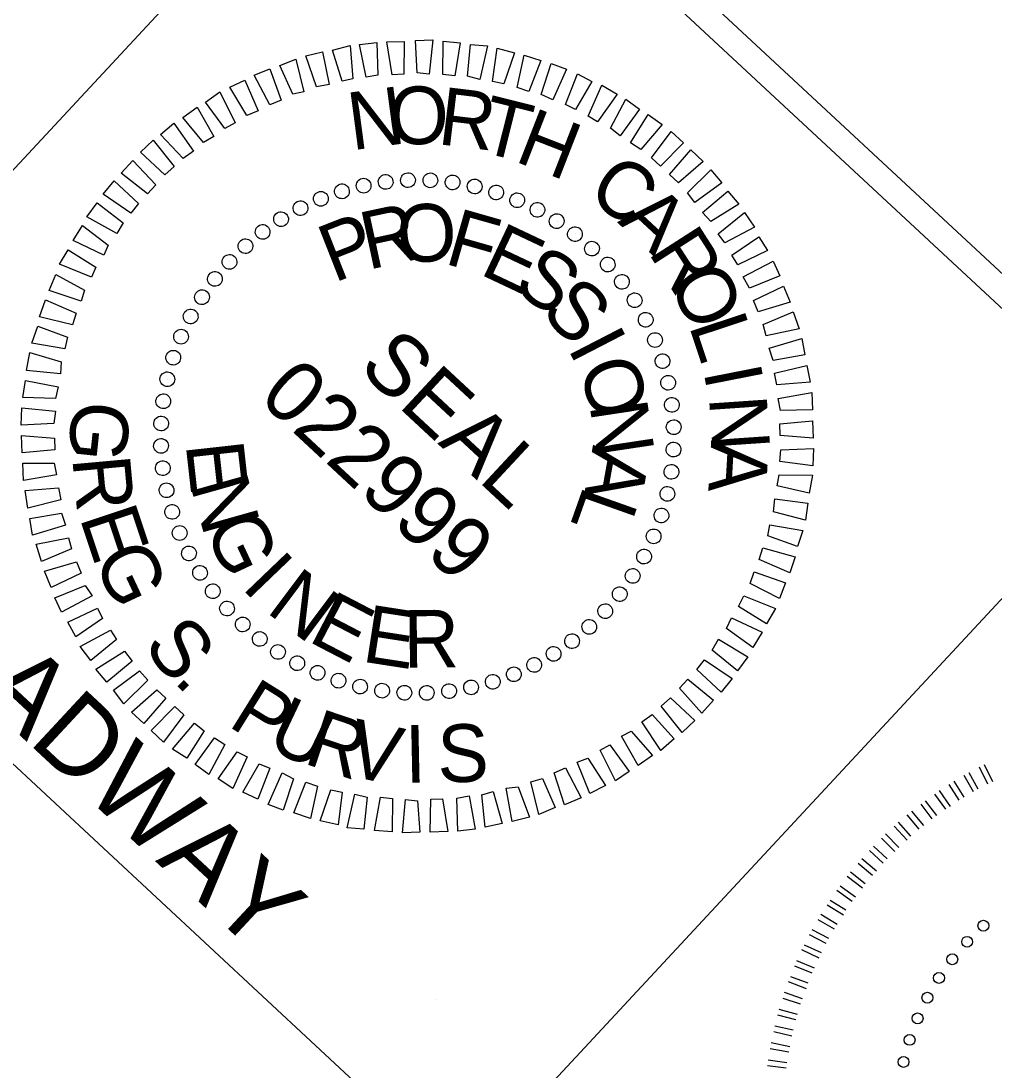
# Model space of a CAD drawing. Extents: x 2057696 to 2061410, y 685900 to 689434.
# Drawn here: x 2059112.8 to 2059188.9, y 688515.7 to 688597.9 of the extents above; entities that cross this region are included whole.
import ezdxf

# ---------------------------------------------------------------- set-up
doc = ezdxf.new("R2010")
doc.units = 0
for name, color, linetype in [('Default', 7, 'Continuous'), ('Exist Vertical Profile Vertical Axis Label', 7, 'Continuous'), ('Prop SS Fill Line', 7, 'Continuous'), ('Prop SS Misc', 7, 'Continuous'), ('Prop Vertical Profile Curve Label', 7, 'Continuous')]:
    doc.layers.add(name, color=color, linetype=linetype)

msp = doc.modelspace()

# ---------------------------------------------------------------- linework, layer by layer
at = {"layer": 'Default'}
for p, q in [((2059256.982, 688512.703), (2058378.024, 689329.669)), ((2059142.648, 688618.973), (2059089.028, 688561.283)), ((2059200.863, 688564.864), (2058628.797, 687949.389)), ((2059089.028, 688561.283), (2059203.361, 688455.014))]:
    msp.add_line(p, q, dxfattribs=at)
msp.add_lwpolyline([(2057714.84, 688796.536), (2058691.069, 687889.16), (2059265.668, 688507.36), (2058289.439, 689414.737)], close=True, dxfattribs=at)
at = {"layer": 'Exist Vertical Profile Vertical Axis Label'}
for p, q in [((2059187.702, 688537.79), (2059186.992, 688539.065)), ((2059188.458, 688538.163), (2059187.799, 688539.492)), ((2059188.849, 688538.363), (2059188.19, 688539.692)), ((2059186.222, 688536.913), (2059185.433, 688538.158)), ((2059186.611, 688537.167), (2059185.822, 688538.411)), ((2059187.339, 688537.565), (2059186.602, 688538.864)), ((2059185.159, 688536.211), (2059184.32, 688537.401)), ((2059185.523, 688536.437), (2059184.681, 688537.68)), ((2059184.099, 688535.456), (2059183.234, 688536.619)), ((2059184.46, 688535.735), (2059183.57, 688536.87)), ((2059183.094, 688534.65), (2059182.15, 688535.783)), ((2059183.455, 688534.928), (2059182.511, 688536.061)), ((2059182.143, 688533.792), (2059181.121, 688534.896)), ((2059182.424, 688534.095), (2059181.455, 688535.2)), ((2059181.501, 688533.212), (2059180.453, 688534.288)), ((2059180.578, 688532.329), (2059179.507, 688533.324)), ((2059181.167, 688532.908), (2059180.147, 688533.958)), ((2059180.272, 688531.999), (2059179.2, 688532.995)), ((2059179.431, 688531.04), (2059178.309, 688531.98)), ((2059179.737, 688531.369), (2059178.588, 688532.336)), ((2059178.645, 688530.029), (2059177.444, 688530.94)), ((2059178.871, 688530.382), (2059177.723, 688531.296)), ((2059178.113, 688529.346), (2059176.914, 688530.205)), ((2059177.834, 688528.991), (2059176.635, 688529.849)), ((2059177.156, 688527.931), (2059175.881, 688528.707)), ((2059177.355, 688528.31), (2059176.132, 688529.088)), ((2059176.453, 688526.844), (2059175.18, 688527.567)), ((2059176.679, 688527.197), (2059175.403, 688527.973)), ((2059176.029, 688526.112), (2059174.704, 688526.78)), ((2059175.805, 688525.706), (2059174.506, 688526.402)), ((2059175.262, 688524.572), (2059173.912, 688525.212)), ((2059175.433, 688524.976), (2059174.111, 688525.591)), ((2059174.893, 688523.789), (2059173.519, 688524.349)), ((2059174.722, 688523.384), (2059173.348, 688523.944)), ((2059174.262, 688522.173), (2059172.863, 688522.706)), ((2059174.406, 688522.603), (2059173.034, 688523.11)), ((2059173.946, 688521.392), (2059172.548, 688521.872)), ((2059173.802, 688520.963), (2059172.432, 688521.417)), ((2059173.448, 688519.755), (2059172.029, 688520.102)), ((2059173.566, 688520.158), (2059172.145, 688520.557)), ((2059173.124, 688518.47), (2059171.705, 688518.816)), ((2059173.24, 688518.925), (2059171.795, 688519.244)), ((2059172.968, 688517.642), (2059171.498, 688517.933)), ((2059172.878, 688517.214), (2059171.435, 688517.479)), ((2059172.685, 688515.959), (2059171.219, 688516.145)), ((2059172.722, 688516.385), (2059171.282, 688516.598))]:
    msp.add_line(p, q, dxfattribs=at)
for centre in [(2059188.109, 688527.102), (2059186.834, 688525.844), (2059185.672, 688524.479), (2059184.634, 688523.018), (2059183.727, 688521.473), (2059182.959, 688519.854), (2059182.334, 688518.174), (2059181.859, 688516.446)]:
    msp.add_circle(centre, 0.425, dxfattribs=at)
at = {"layer": 'Prop SS Misc'}
for p, q in [((2059139.656, 688585.001), (2059139.656, 688585.001)), ((2059141.344, 688585.289), (2059141.344, 688585.289)), ((2059143.094, 688585.409), (2059143.094, 688585.409)), ((2059144.849, 688585.417), (2059144.849, 688585.417)), ((2059146.582, 688585.225), (2059146.582, 688585.225)), ((2059137.918, 688584.541), (2059137.918, 688584.541)), ((2059148.32, 688584.921), (2059148.32, 688584.921)), ((2059150.007, 688584.445), (2059150.007, 688584.445)), ((2059136.297, 688583.972), (2059136.297, 688583.972)), ((2059151.669, 688583.883), (2059151.669, 688583.883)), ((2059134.71, 688583.263), (2059134.71, 688583.263)), ((2059153.226, 688583.091), (2059153.226, 688583.091)), ((2059133.185, 688582.387), (2059133.185, 688582.387)), ((2059154.759, 688582.213), (2059154.759, 688582.213)), ((2059131.723, 688581.342), (2059131.723, 688581.342)), ((2059156.182, 688581.218), (2059156.182, 688581.218)), ((2059130.404, 688580.275), (2059130.404, 688580.275)), ((2059157.525, 688580.078), (2059157.525, 688580.078)), ((2059129.147, 688579.041), (2059129.147, 688579.041)), ((2059158.76, 688578.821), (2059158.76, 688578.821)), ((2059128.007, 688577.697), (2059128.007, 688577.697)), ((2059159.857, 688577.474), (2059159.857, 688577.474)), ((2059126.985, 688576.245), (2059126.985, 688576.245)), ((2059160.844, 688576.01), (2059160.844, 688576.01)), ((2059126.105, 688574.769), (2059126.105, 688574.769)), ((2059161.748, 688574.515), (2059161.748, 688574.515)), ((2059125.342, 688573.184), (2059125.342, 688573.184)), ((2059162.43, 688572.898), (2059162.43, 688572.898)), ((2059124.751, 688571.549), (2059124.751, 688571.549)), ((2059163.028, 688571.25), (2059163.028, 688571.25)), ((2059124.248, 688569.833), (2059124.248, 688569.833)), ((2059163.458, 688569.54), (2059163.458, 688569.54)), ((2059123.97, 688568.125), (2059123.97, 688568.125)), ((2059163.776, 688567.825), (2059163.776, 688567.825)), ((2059123.752, 688566.362), (2059123.752, 688566.362)), ((2059163.896, 688566.074), (2059163.896, 688566.074)), ((2059143.855, 688565.37), (2059143.855, 688565.37)), ((2059123.759, 688564.607), (2059123.759, 688564.607)), ((2059163.904, 688564.32), (2059163.904, 688564.32)), ((2059123.88, 688562.857), (2059123.88, 688562.857)), ((2059163.74, 688562.616), (2059163.74, 688562.616)), ((2059124.197, 688561.142), (2059124.197, 688561.142)), ((2059163.408, 688560.849), (2059163.408, 688560.849)), ((2059124.628, 688559.431), (2059124.628, 688559.431)), ((2059162.959, 688559.191), (2059162.959, 688559.191)), ((2059125.226, 688557.783), (2059125.226, 688557.783)), ((2059162.368, 688557.556), (2059162.368, 688557.556)), ((2059125.962, 688556.225), (2059125.962, 688556.225)), ((2059161.605, 688555.971), (2059161.605, 688555.971)), ((2059126.811, 688554.671), (2059126.811, 688554.671)), ((2059160.67, 688554.437), (2059160.67, 688554.437)), ((2059127.853, 688553.266), (2059127.853, 688553.266)), ((2059159.702, 688553.043), (2059159.702, 688553.043)), ((2059128.95, 688551.919), (2059128.95, 688551.919)), ((2059158.563, 688551.7), (2059158.563, 688551.7)), ((2059130.184, 688550.662), (2059130.184, 688550.662)), ((2059157.306, 688550.465), (2059157.306, 688550.465)), ((2059131.528, 688549.523), (2059131.528, 688549.523)), ((2059155.932, 688549.339), (2059155.932, 688549.339)), ((2059132.951, 688548.527), (2059132.951, 688548.527)), ((2059154.525, 688548.354), (2059154.525, 688548.354)), ((2059134.429, 688547.591), (2059134.429, 688547.591)), ((2059153, 688547.477), (2059153, 688547.477)), ((2059136.041, 688546.857), (2059136.041, 688546.857)), ((2059151.413, 688546.768), (2059151.413, 688546.768)), ((2059137.648, 688546.237), (2059137.648, 688546.237)), ((2059139.336, 688545.761), (2059139.336, 688545.761)), ((2059148.054, 688545.74), (2059148.054, 688545.74)), ((2059149.737, 688546.141), (2059149.737, 688546.141)), ((2059141.073, 688545.456), (2059141.073, 688545.456)), ((2059142.807, 688545.265), (2059142.807, 688545.265)), ((2059144.561, 688545.272), (2059144.561, 688545.272)), ((2059146.312, 688545.393), (2059146.312, 688545.393)), ((2059145.295, 688521.326), (2059145.295, 688521.326))]:
    msp.add_line(p, q, dxfattribs=at)
for points in [[(2059137.943, 688593.146), (2059137.203, 688595.581), (2059138.577, 688595.943), (2059138.785, 688593.346)], [(2059139.828, 688593.469), (2059139.31, 688596.026), (2059140.662, 688596.189), (2059140.728, 688593.616)], [(2059141.859, 688593.657), (2059141.454, 688596.218), (2059142.81, 688596.267), (2059142.763, 688593.69)], [(2059143.806, 688593.813), (2059143.686, 688596.328), (2059145.042, 688596.377), (2059144.744, 688593.706)], [(2059145.82, 688593.688), (2059145.838, 688596.293), (2059147.174, 688596.144), (2059146.758, 688593.581)], [(2059147.75, 688593.533), (2059147.998, 688596.032), (2059149.305, 688595.91), (2059148.722, 688593.285)], [(2059149.718, 688593.123), (2059150.075, 688595.74), (2059151.419, 688595.365), (2059150.602, 688592.958)], [(2059134.103, 688592.128), (2059133.086, 688594.383), (2059134.314, 688594.881), (2059134.945, 688592.329)], [(2059135.95, 688592.705), (2059135.097, 688595.136), (2059136.416, 688595.439), (2059136.934, 688592.883)], [(2059151.632, 688592.656), (2059152.19, 688595.195), (2059153.479, 688594.761), (2059152.548, 688592.349)], [(2059132.293, 688591.298), (2059131.076, 688593.631), (2059132.303, 688594.128), (2059133.186, 688591.67)], [(2059153.52, 688592.102), (2059154.308, 688594.537), (2059155.485, 688594.098), (2059154.441, 688591.683)], [(2059130.484, 688590.467), (2059129.158, 688592.683), (2059130.326, 688593.235), (2059131.376, 688590.84)], [(2059155.416, 688591.322), (2059156.347, 688593.734), (2059157.473, 688593.124), (2059156.195, 688590.926)], [(2059157.204, 688590.425), (2059158.248, 688592.841), (2059159.462, 688592.149), (2059157.928, 688589.971)], [(2059128.767, 688589.442), (2059127.248, 688591.51), (2059128.379, 688592.315), (2059129.571, 688589.896)], [(2059158.937, 688589.47), (2059160.127, 688591.749), (2059161.203, 688590.968), (2059159.695, 688588.875)], [(2059127.108, 688588.363), (2059125.48, 688590.313), (2059126.611, 688591.118), (2059127.912, 688588.817)], [(2059160.507, 688588.338), (2059161.898, 688590.54), (2059162.974, 688589.759), (2059161.319, 688587.802)], [(2059125.512, 688587.116), (2059123.746, 688588.976), (2059124.789, 688589.863), (2059126.312, 688587.683)], [(2059162.135, 688587.152), (2059163.673, 688589.218), (2059164.64, 688588.32), (2059162.838, 688586.499)], [(2059124.088, 688585.818), (2059122.183, 688587.588), (2059123.168, 688588.53), (2059124.8, 688586.467)], [(2059163.541, 688585.845), (2059165.226, 688587.775), (2059166.192, 688586.876), (2059164.245, 688585.192)], [(2059122.726, 688584.353), (2059120.658, 688585.948), (2059121.584, 688586.944), (2059123.38, 688585.057)], [(2059164.952, 688584.425), (2059166.783, 688586.219), (2059167.64, 688585.203), (2059165.546, 688583.654)], [(2059121.423, 688582.834), (2059119.246, 688584.311), (2059120.114, 688585.362), (2059122.018, 688583.592)], [(2059166.14, 688582.884), (2059168.118, 688584.541), (2059168.975, 688583.525), (2059166.789, 688582.171)], [(2059120.321, 688581.237), (2059117.981, 688582.538), (2059118.79, 688583.643), (2059120.828, 688582.076)], [(2059167.362, 688581.202), (2059169.423, 688582.89), (2059170.202, 688581.73), (2059167.869, 688580.513)], [(2059119.307, 688579.558), (2059116.916, 688580.688), (2059117.637, 688581.875), (2059119.646, 688580.335)], [(2059168.442, 688579.543), (2059170.54, 688580.978), (2059171.231, 688579.9), (2059168.894, 688578.795)], [(2059118.351, 688577.825), (2059115.852, 688578.838), (2059116.518, 688579.966), (2059118.691, 688578.602)], [(2059169.324, 688577.849), (2059171.657, 688579.066), (2059172.18, 688577.925), (2059169.81, 688576.961)], [(2059117.542, 688575.956), (2059115.022, 688576.77), (2059115.542, 688578.034), (2059117.794, 688576.814)], [(2059170.128, 688576.01), (2059172.465, 688577.114), (2059172.992, 688575.86), (2059170.5, 688575.118)], [(2059116.846, 688574.091), (2059114.276, 688574.733), (2059114.737, 688576.052), (2059117.152, 688575.008)], [(2059170.876, 688574.113), (2059173.217, 688575.104), (2059173.69, 688573.791), (2059171.106, 688573.244)], [(2059116.263, 688572.23), (2059113.672, 688572.673), (2059114.133, 688573.992), (2059116.456, 688573.143)], [(2059171.34, 688572.262), (2059173.916, 688573.035), (2059174.133, 688571.741), (2059171.658, 688571.311)], [(2059115.911, 688570.264), (2059113.269, 688570.535), (2059113.529, 688571.932), (2059115.961, 688571.2)], [(2059171.779, 688570.325), (2059174.304, 688570.927), (2059174.551, 688569.605), (2059171.954, 688569.397)], [(2059115.529, 688568.325), (2059112.979, 688568.402), (2059113.184, 688569.74), (2059115.722, 688569.238)], [(2059172.05, 688568.325), (2059174.693, 688568.818), (2059174.742, 688567.461), (2059172.225, 688567.398)], [(2059115.402, 688566.368), (2059112.831, 688566.246), (2059112.894, 688567.606), (2059115.537, 688567.335)], [(2059172.179, 688566.349), (2059174.746, 688566.584), (2059174.795, 688565.227), (2059172.212, 688565.444)], [(2059115.476, 688564.333), (2059112.909, 688564.097), (2059112.86, 688565.454), (2059115.443, 688565.237)], [(2059172.253, 688564.314), (2059174.824, 688564.436), (2059174.761, 688563.075), (2059172.173, 688563.405)], [(2059115.605, 688562.356), (2059113.017, 688561.922), (2059112.968, 688563.279), (2059115.43, 688563.284)], [(2059172.127, 688562.356), (2059174.731, 688562.338), (2059174.471, 688560.942), (2059171.988, 688561.502)], [(2059115.931, 688560.415), (2059113.351, 688559.755), (2059113.159, 688561.135), (2059115.756, 688561.343)], [(2059171.799, 688560.476), (2059174.387, 688560.146), (2059174.181, 688558.808), (2059171.694, 688559.482)], [(2059116.315, 688558.42), (2059113.74, 688557.646), (2059113.523, 688558.94), (2059115.997, 688559.37)], [(2059171.392, 688558.452), (2059173.984, 688558.009), (2059173.577, 688556.749), (2059171.253, 688557.598)], [(2059116.779, 688556.569), (2059114.438, 688555.577), (2059114.02, 688556.949), (2059116.549, 688557.438)], [(2059170.864, 688556.649), (2059173.38, 688555.949), (2059172.973, 688554.689), (2059170.557, 688555.733)], [(2059117.528, 688554.671), (2059115.191, 688553.567), (2059114.664, 688554.822), (2059117.156, 688555.564)], [(2059170.168, 688554.784), (2059172.634, 688553.912), (2059172.168, 688552.706), (2059169.861, 688553.867)], [(2059118.385, 688552.891), (2059115.998, 688551.615), (2059115.475, 688552.757), (2059117.846, 688553.721)], [(2059169.358, 688552.915), (2059171.858, 688551.903), (2059171.137, 688550.716), (2059168.964, 688552.08)], [(2059119.214, 688551.139), (2059117.115, 688549.703), (2059116.479, 688550.841), (2059118.816, 688551.945)], [(2059168.403, 688551.182), (2059170.793, 688550.052), (2059170.073, 688548.865), (2059168.009, 688550.347)], [(2059120.293, 688549.48), (2059118.287, 688547.85), (2059117.454, 688548.952), (2059119.841, 688550.228)], [(2059167.389, 688549.503), (2059169.674, 688548.143), (2059168.866, 688547.038), (2059166.882, 688548.664)], [(2059121.515, 688547.798), (2059119.538, 688546.141), (2059118.68, 688547.157), (2059120.921, 688548.569)], [(2059166.287, 688547.906), (2059168.463, 688546.429), (2059167.596, 688545.379), (2059165.692, 688547.149)], [(2059122.758, 688546.315), (2059120.873, 688544.463), (2059120.069, 688545.538), (2059122.109, 688547.027)], [(2059164.984, 688546.387), (2059166.997, 688544.734), (2059166.071, 688543.738), (2059164.33, 688545.684)], [(2059124.168, 688544.895), (2059122.43, 688542.907), (2059121.463, 688543.805), (2059123.465, 688545.548)], [(2059163.622, 688544.922), (2059165.526, 688543.152), (2059164.542, 688542.21), (2059162.91, 688544.273)], [(2059125.575, 688543.588), (2059123.983, 688541.463), (2059123.016, 688542.362), (2059124.872, 688544.241)], [(2059162.198, 688543.625), (2059163.909, 688541.706), (2059162.866, 688540.819), (2059161.398, 688543.058)], [(2059127.149, 688542.343), (2059125.812, 688540.2), (2059124.682, 688540.923), (2059126.391, 688542.938)], [(2059160.547, 688542.319), (2059162.23, 688540.427), (2059161.099, 688539.622), (2059159.798, 688541.923)], [(2059128.773, 688541.271), (2059127.528, 688538.933), (2059126.452, 688539.714), (2059127.961, 688541.807)], [(2059130.506, 688540.315), (2059129.408, 688537.841), (2059128.248, 688538.591), (2059129.727, 688540.711)], [(2059158.889, 688541.239), (2059160.408, 688539.172), (2059159.331, 688538.425), (2059158.139, 688540.844)], [(2059157.171, 688540.214), (2059158.552, 688538.057), (2059157.329, 688537.446), (2059156.334, 688539.901)], [(2059132.294, 688539.418), (2059131.363, 688537.007), (2059130.182, 688537.558), (2059131.46, 688539.756)], [(2059134.136, 688538.58), (2059133.347, 688536.145), (2059132.171, 688536.583), (2059133.269, 688539.057)], [(2059155.416, 688539.442), (2059156.634, 688537.11), (2059155.352, 688536.553), (2059154.524, 688539.07)], [(2059136.024, 688538.026), (2059135.466, 688535.487), (2059134.176, 688535.921), (2059135.107, 688538.332)], [(2059153.607, 688538.612), (2059154.623, 688536.357), (2059153.342, 688535.8), (2059152.711, 688538.353)], [(2059137.937, 688537.558), (2059137.635, 688535), (2059136.236, 688535.317), (2059137.054, 688537.724)], [(2059139.905, 688537.149), (2059139.657, 688534.649), (2059138.35, 688534.771), (2059138.934, 688537.397)], [(2059149.767, 688537.594), (2059150.452, 688535.1), (2059149.133, 688534.798), (2059148.87, 688537.335)], [(2059151.706, 688537.977), (2059152.613, 688535.604), (2059151.239, 688535.242), (2059150.776, 688537.858)], [(2059141.89, 688537.052), (2059141.872, 688534.447), (2059140.482, 688534.538), (2059140.952, 688537.159)], [(2059143.85, 688536.869), (2059144.024, 688534.413), (2059142.667, 688534.363), (2059142.912, 688536.976)], [(2059145.797, 688537.025), (2059146.202, 688534.464), (2059144.845, 688534.414), (2059144.892, 688536.992)], [(2059147.882, 688537.271), (2059148.346, 688534.656), (2059146.993, 688534.493), (2059146.927, 688537.066)]]:
    msp.add_lwpolyline(points, close=True, dxfattribs=at)
for centre, major_axis in [((2059141.353, 688585.271), (-0.071, 0.572)), ((2059143.097, 688585.411), (-0.021, 0.576)), ((2059144.848, 688585.398), (0.029, 0.575)), ((2059146.59, 688585.234), (0.079, 0.571)), ((2059137.933, 688584.538), (-0.169, 0.551)), ((2059139.627, 688584.979), (-0.121, 0.563)), ((2059148.312, 688584.917), (0.129, 0.561)), ((2059149.999, 688584.452), (0.177, 0.548)), ((2059136.284, 688583.951), (-0.217, 0.534)), ((2059151.64, 688583.842), (0.224, 0.531)), ((2059134.692, 688583.223), (-0.262, 0.513)), ((2059153.221, 688583.091), (0.27, 0.509)), ((2059133.17, 688582.358), (-0.306, 0.488)), ((2059154.73, 688582.205), (0.313, 0.484)), ((2059131.729, 688581.364), (-0.347, 0.459)), ((2059156.157, 688581.191), (0.354, 0.454)), ((2059130.381, 688580.249), (-0.386, 0.427)), ((2059157.49, 688580.056), (0.392, 0.422)), ((2059129.134, 688579.02), (-0.422, 0.392)), ((2059158.719, 688578.81), (0.427, 0.386)), ((2059127.999, 688577.687), (-0.454, 0.354)), ((2059159.834, 688577.461), (0.459, 0.347)), ((2059126.985, 688576.26), (-0.484, 0.313)), ((2059160.828, 688576.02), (0.488, 0.306)), ((2059126.099, 688574.751), (-0.509, 0.27)), ((2059161.693, 688574.498), (0.513, 0.262)), ((2059125.348, 688573.17), (-0.531, 0.224)), ((2059162.421, 688572.907), (0.534, 0.217)), ((2059124.738, 688571.529), (-0.548, 0.177)), ((2059163.008, 688571.258), (0.551, 0.169)), ((2059124.273, 688569.842), (-0.561, 0.129)), ((2059163.449, 688569.564), (0.563, 0.121)), ((2059123.957, 688568.12), (-0.571, 0.079)), ((2059163.741, 688567.838), (0.572, 0.071)), ((2059123.792, 688566.378), (-0.575, 0.029)), ((2059163.881, 688566.093), (0.576, 0.021)), ((2059123.78, 688564.627), (-0.576, -0.021)), ((2059163.868, 688564.343), (0.575, -0.029)), ((2059123.92, 688562.883), (-0.572, -0.071)), ((2059163.704, 688562.6), (0.571, -0.079)), ((2059124.212, 688561.157), (-0.563, -0.121)), ((2059163.387, 688560.879), (0.561, -0.129)), ((2059124.653, 688559.463), (-0.551, -0.169)), ((2059162.922, 688559.191), (0.548, -0.177)), ((2059125.24, 688557.814), (-0.534, -0.217)), ((2059162.312, 688557.551), (0.531, -0.224)), ((2059125.968, 688556.222), (-0.513, -0.262)), ((2059161.561, 688555.97), (0.509, -0.27)), ((2059126.832, 688554.7), (-0.488, -0.306)), ((2059160.675, 688554.46), (0.484, -0.313)), ((2059127.826, 688553.259), (-0.459, -0.347)), ((2059159.661, 688553.033), (0.454, -0.354)), ((2059128.942, 688551.911), (-0.427, -0.386)), ((2059158.526, 688551.701), (0.422, -0.392)), ((2059130.171, 688550.664), (-0.392, -0.422)), ((2059157.28, 688550.472), (0.386, -0.427)), ((2059131.503, 688549.529), (-0.354, -0.454)), ((2059155.931, 688549.356), (0.347, -0.459)), ((2059132.93, 688548.515), (-0.313, -0.484)), ((2059154.49, 688548.362), (0.306, -0.488)), ((2059134.44, 688547.629), (-0.27, -0.509)), ((2059152.968, 688547.498), (0.262, -0.513)), ((2059136.021, 688546.878), (-0.224, -0.531)), ((2059151.377, 688546.77), (0.217, -0.534)), ((2059137.661, 688546.268), (-0.177, -0.548)), ((2059139.349, 688545.803), (-0.129, -0.561)), ((2059148.034, 688545.742), (0.121, -0.563)), ((2059149.728, 688546.183), (0.169, -0.551)), ((2059141.07, 688545.487), (-0.079, -0.571)), ((2059142.813, 688545.322), (-0.029, -0.575)), ((2059144.563, 688545.31), (0.021, -0.576)), ((2059146.308, 688545.45), (0.071, -0.572))]:
    msp.add_ellipse(centre, major_axis=major_axis, ratio=0.999708, dxfattribs=at)
at = {"layer": 'Prop Vertical Profile Curve Label'}
msp.add_lwpolyline([(2058210.314, 688884.84), (2058901.309, 688242.579), (2059147.243, 688507.174), (2059089.028, 688561.283), (2059142.648, 688618.973), (2058378.024, 689329.669), (2058078.47, 689007.384), (2058137.067, 688952.92)], dxfattribs=at)

# ---------------------------------------------------------------- texts
at = {"layer": 'Default'}
msp.add_text('ROADWAY', height=6.1288, rotation=317.09343, dxfattribs=at).set_placement((2059100.286, 688553.555))
at = {"layer": 'Prop SS Fill Line'}
for s, height, p in [('INCOMPLETE PLANS', 9.6, (2059170.063, 688645.207)), ('DO NOT USE FOR R/W ACQUISITION', 4.8, (2059167.964, 688639.251))]:
    msp.add_text(s, height=height, rotation=317.09343, dxfattribs=at).set_placement(p)
at = {"layer": 'Prop SS Misc'}
for s, height, rotation, p in [('N', 4.511, 7.51693, (2059138.707, 688587.74)), ('O', 4.511, 0.31517, (2059141.605, 688588.213)), ('R', 4.511, 353.11394, (2059145.34, 688588.237)), ('T', 4.511, 345.9132, (2059148.501, 688587.701)), ('H', 4.511, 338.71291, (2059151.331, 688586.927)), ('C', 4.51, 324.3133, (2059156.954, 688584.104)), ('A', 4.51, 317.11375, (2059159.432, 688582.129)), ('R', 4.511, 12.13308, (2059139.954, 688578.389)), ('O', 4.511, 2.77467, (2059142.312, 688578.928)), ('P', 4.511, 21.49232, (2059137.303, 688577.358)), ('F', 4.511, 344.06047, (2059145.85, 688578.915)), ('E', 4.511, 334.7045, (2059148.597, 688578.11)), ('R', 4.511, 302.71453, (2059161.838, 688579.783)), ('S', 4.51, 325.34904, (2059151.188, 688576.903)), ('O', 4.511, 295.5146, (2059163.42, 688577.548)), ('S', 4.51, 315.99383, (2059153.352, 688575.001)), ('L', 4.511, 288.31431, (2059165.047, 688574.07)), ('I', 4.511, 297.28303, (2059155.545, 688572.307)), ('SEAL', 4.7986, 317.09343, (2059139.105, 688570.659)), ('022999', 4.8, 317.09343, (2059131.289, 688568.312)), ('O', 4.511, 287.92692, (2059156.365, 688570.78)), ('I', 4.51, 281.11357, (2059166.197, 688570.489)), ('G', 4.512, 264.03441, (2059116.949, 688568.304)), ('N', 4.511, 278.57004, (2059157.293, 688567.843)), ('N', 4.511, 273.91234, (2059166.64, 688568.439)), ('E', 4.51, 276.37032, (2059125.706, 688564.763)), ('A', 4.511, 259.8537, (2059157.577, 688564.74)), ('A', 4.511, 266.71058, (2059166.818, 688565.106)), ('R', 4.512, 275.20706, (2059116.831, 688563.688)), ('N', 4.511, 285.72739, (2059126.048, 688561.606)), ('L', 4.512, 250.49428, (2059156.897, 688561.658)), ('E', 4.512, 288.43104, (2059117.387, 688559.039)), ('G', 4.511, 295.08367, (2059127.106, 688558.22)), ('G', 4.512, 295.04303, (2059118.422, 688555.826)), ('I', 4.51, 313.79463, (2059129.993, 688553.57)), ('N', 4.51, 323.14982, (2059131.902, 688551.687)), ('E', 4.51, 332.50519, (2059135.183, 688549.401)), ('E', 4.511, 351.21752, (2059139.404, 688547.773)), ('R', 4.511, 0.57484, (2059142.762, 688547.273)), ('S', 4.512, 308.26701, (2059122.292, 688548.987)), ('.', 4.512, 314.879, (2059124.686, 688546.216)), ('P', 4.512, 328.10298, (2059128.916, 688542.776)), ('U', 4.512, 334.71497, (2059131.879, 688541.097)), ('R', 4.512, 341.32696, (2059134.819, 688539.845)), ('V', 4.512, 347.93895, (2059138.119, 688538.908)), ('I', 4.512, 1.16292, (2059142.885, 688538.268)), ('S', 4.512, 1.16292, (2059145.431, 688538.306))]:
    msp.add_text(s, height=height, rotation=rotation, dxfattribs=at).set_placement(p)

doc.saveas('drawing.dxf')
